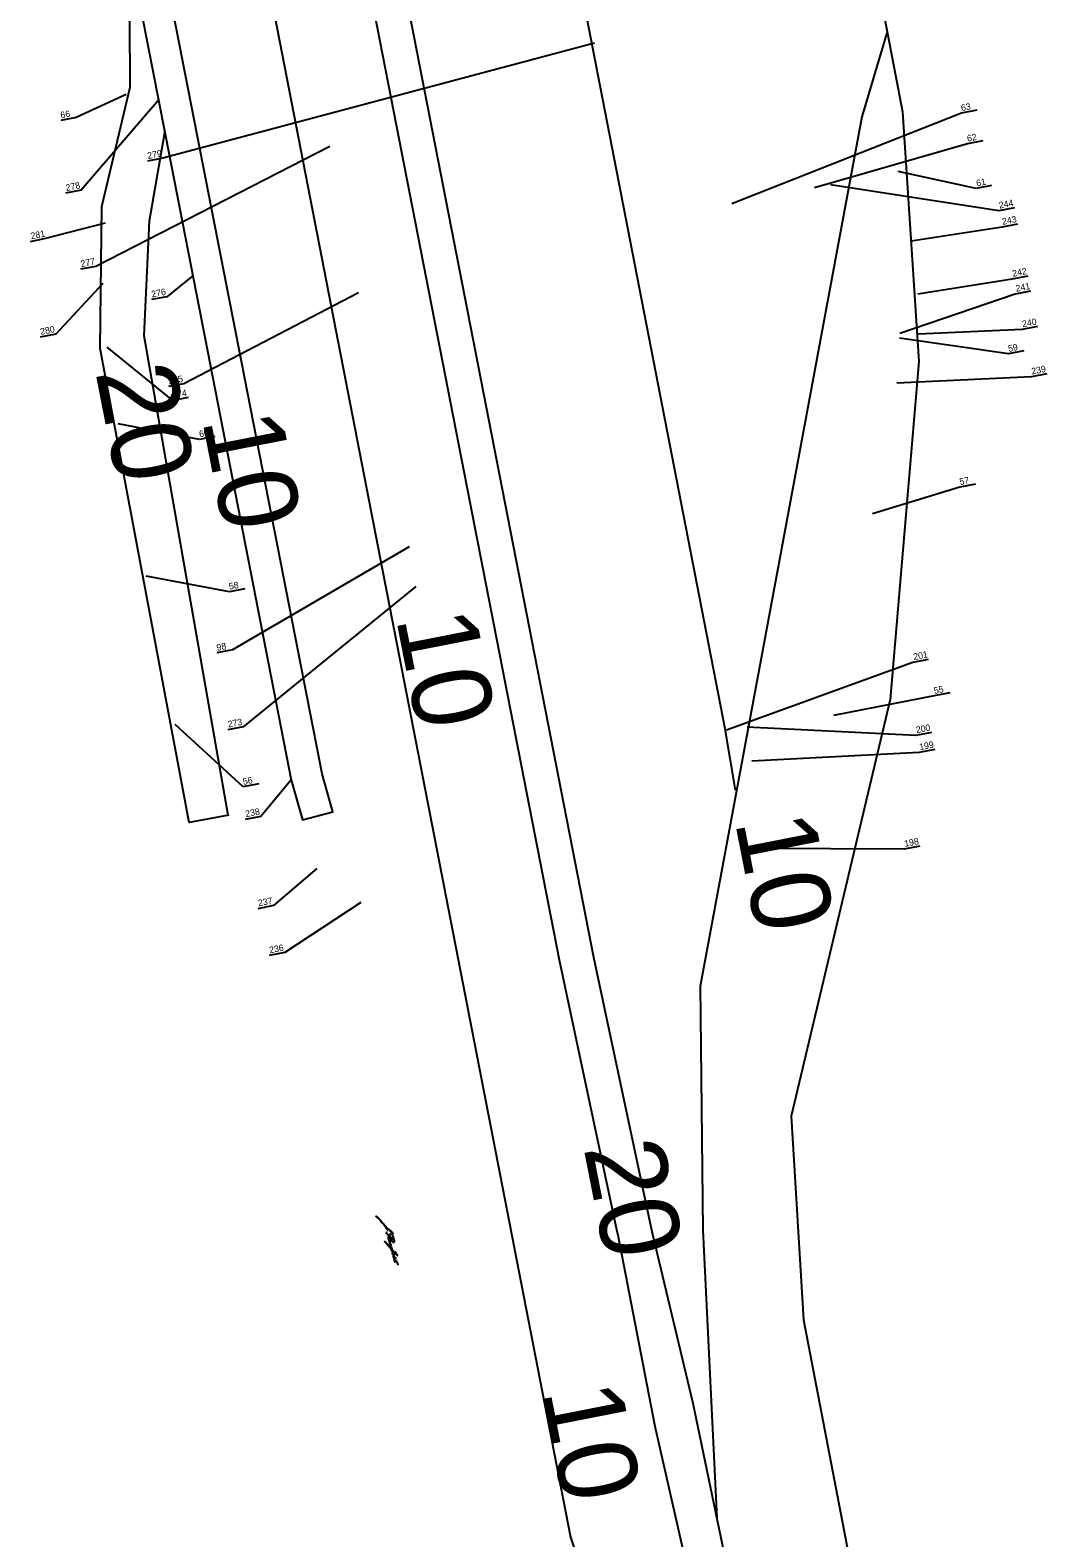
# Model space of a CAD drawing. Extents: x -545967 to -545044, y -1122650 to -1118491.
# Drawn here: x -545644.5 to -545352.2, y -1120534.8 to -1120101.4 of the extents above; entities that cross this region are included whole.
import ezdxf

# ---------------------------------------------------------------- set-up
doc = ezdxf.new("R2010")
doc.units = 0
for name, color, linetype in [('osvětlené plochy-hodnota-obrys', 7, 'Continuous'), ('so180602', 7, 'Continuous'), ('Vrstva 63', 7, 'Continuous')]:
    doc.layers.add(name, color=color, linetype=linetype)

msp = doc.modelspace()

# ---------------------------------------------------------------- linework, layer by layer
at = {"layer": 'osvětlené plochy-hodnota-obrys'}
for points in [[(-545520.97, -1119506.47), (-545505.64, -1119546.72), (-545397.93, -1120102.85)], [(-545441.66, -1120319.91), (-545444.67, -1120302.28), (-545584.85, -1119581.02)], [(-545607.52, -1119727.52), (-545482.54, -1120367.87), (-545465.73, -1120446.74)], [(-545611.11, -1119760.37), (-545492.39, -1120368.61), (-545475.58, -1120447.49)], [(-545605.8, -1119934.36), (-545489.14, -1120534.59)], [(-545587.34, -1120327.06), (-545598.8, -1120329.21), (-545624.38, -1120192.88), (-545623.87, -1120152.06), (-545615.74, -1120117.75), (-545615.95, -1120078.59)], [(-545615.95, -1120078.72), (-545593.53, -1120193.57), (-545569.43, -1120317.04), (-545566.21, -1120328.42), (-545557.45, -1120326.08), (-545560.55, -1120315.17), (-545604.97, -1120087.82)], [(-545398.15, -1120102.16), (-545405.36, -1120126.29), (-545451.85, -1120376.21), (-545451.08, -1120446.35), (-545447.1, -1120529.01)], [(-545397.93, -1120102.85), (-545393.73, -1120124.86), (-545389.03, -1120196.69), (-545397.24, -1120293.85), (-545425.66, -1120413.56)], [(-545587.57, -1120327.02), (-545611.68, -1120189.23), (-545610.12, -1120156.2), (-545605.75, -1120130.8)], [(-545425.66, -1120413.56), (-545422.17, -1120472.14), (-545406.82, -1120552), (-545405.96, -1120682.12)], [(-545413.7, -1120747.46), (-545423.75, -1120695.7), (-545432.65, -1120651.38), (-545447.75, -1120577.89), (-545464.8, -1120502.77), (-545475.48, -1120447.29)], [(-545465.73, -1120446.74), (-545453.92, -1120496.13), (-545438.94, -1120568.39), (-545416.42, -1120682.47), (-545404.15, -1120745.59), (-545418.01, -1120748.3)], [(-545489.14, -1120534.59), (-545478.74, -1120565.98), (-545448.6, -1120720.36), (-545424.84, -1120715.84), (-545418.01, -1120748.3)]]:
    msp.add_lwpolyline(points, dxfattribs=at)
at = {"layer": 'Vrstva 63'}
for p, q in [((-545482.24, -1120105.1), (-545606.32, -1120138.21)), ((-545616.89, -1120119.89), (-545631.2, -1120126.49)), ((-545607.45, -1120121.42), (-545629.82, -1120147.42)), ((-545631.2, -1120126.49), (-545635.64, -1120127.35)), ((-545376.75, -1120125.28), (-545442.71, -1120151.28)), ((-545372.3, -1120124.42), (-545376.75, -1120125.28)), ((-545558.3, -1120134.85), (-545625.54, -1120169.29)), ((-545375.03, -1120134.05), (-545418.99, -1120146.74)), ((-545370.58, -1120133.19), (-545375.03, -1120134.05)), ((-545606.32, -1120138.21), (-545610.77, -1120139.07)), ((-545372.51, -1120146.94), (-545394.9, -1120141.99)), ((-545629.82, -1120147.42), (-545634.26, -1120148.28)), ((-545365.97, -1120153.35), (-545414.36, -1120145.87)), ((-545368.06, -1120146.07), (-545372.51, -1120146.94)), ((-545361.52, -1120152.48), (-545365.97, -1120153.35)), ((-545361.52, -1120152.48), (-545365.97, -1120153.35)), ((-545361.52, -1120152.48), (-545365.97, -1120153.35)), ((-545622.91, -1120156.86), (-545640.02, -1120161.33)), ((-545360.61, -1120157.14), (-545365.06, -1120158)), ((-545360.61, -1120157.14), (-545365.06, -1120158)), ((-545360.61, -1120157.14), (-545365.06, -1120158)), ((-545640.02, -1120161.33), (-545644.47, -1120162.2)), ((-545365.06, -1120158), (-545391.23, -1120162.02)), ((-545625.54, -1120169.29), (-545629.98, -1120170.15)), ((-545623.59, -1120174.2), (-545637.13, -1120188.76)), ((-545597.59, -1120171.95), (-545605.17, -1120178.01)), ((-545362.13, -1120172.95), (-545389.25, -1120177.3)), ((-545357.69, -1120172.08), (-545362.13, -1120172.95)), ((-545357.69, -1120172.08), (-545362.13, -1120172.95)), ((-545357.69, -1120172.08), (-545362.13, -1120172.95)), ((-545605.17, -1120178.01), (-545609.61, -1120178.87)), ((-545550.1, -1120176.89), (-545600.27, -1120203.02)), ((-545361.28, -1120177.28), (-545394.41, -1120188.57)), ((-545356.84, -1120176.41), (-545361.28, -1120177.28)), ((-545356.84, -1120176.41), (-545361.28, -1120177.28)), ((-545356.84, -1120176.41), (-545361.28, -1120177.28)), ((-545359.29, -1120187.46), (-545389.1, -1120188.76)), ((-545354.85, -1120186.59), (-545359.29, -1120187.46)), ((-545354.85, -1120186.59), (-545359.29, -1120187.46)), ((-545354.85, -1120186.59), (-545359.29, -1120187.46)), ((-545637.13, -1120188.76), (-545641.57, -1120189.62)), ((-545363.2, -1120194.47), (-545394.52, -1120189.9)), ((-545603.46, -1120207.9), (-545622.34, -1120192.53)), ((-545358.76, -1120193.61), (-545363.2, -1120194.47)), ((-545356.63, -1120201.04), (-545395.27, -1120202.86)), ((-545352.19, -1120200.18), (-545356.63, -1120201.04)), ((-545352.19, -1120200.18), (-545356.63, -1120201.04)), ((-545352.19, -1120200.18), (-545356.63, -1120201.04)), ((-545600.27, -1120203.02), (-545604.72, -1120203.88)), ((-545599.02, -1120207.04), (-545603.46, -1120207.9)), ((-545595.77, -1120219.04), (-545619.18, -1120214.58)), ((-545591.33, -1120218.18), (-545595.77, -1120219.04)), ((-545377.19, -1120232.74), (-545402.34, -1120240.43)), ((-545372.74, -1120231.87), (-545377.19, -1120232.74)), ((-545535.49, -1120249.95), (-545586.32, -1120279.55)), ((-545587.2, -1120262.84), (-545611.1, -1120258.33)), ((-545533.62, -1120261.28), (-545583.22, -1120301.65)), ((-545582.76, -1120261.98), (-545587.2, -1120262.84)), ((-545586.32, -1120279.55), (-545590.76, -1120280.41)), ((-545390.7, -1120283.15), (-545444.25, -1120302.61)), ((-545386.26, -1120282.29), (-545390.7, -1120283.15)), ((-545386.26, -1120282.29), (-545390.7, -1120283.15)), ((-545380.1, -1120291.94), (-545384.54, -1120292.8)), ((-545384.54, -1120292.8), (-545413.56, -1120298.38)), ((-545583.19, -1120318.95), (-545602.77, -1120301.01)), ((-545583.22, -1120301.65), (-545587.66, -1120302.52)), ((-545389.82, -1120304.15), (-545438.31, -1120301.8)), ((-545385.37, -1120303.28), (-545389.82, -1120304.15)), ((-545385.37, -1120303.28), (-545389.82, -1120304.15)), ((-545388.86, -1120309.03), (-545436.99, -1120311.56)), ((-545384.41, -1120308.17), (-545388.86, -1120309.03)), ((-545384.41, -1120308.17), (-545388.86, -1120309.03)), ((-545578.75, -1120318.08), (-545583.19, -1120318.95)), ((-545569.33, -1120316.8), (-545578.17, -1120327.42)), ((-545578.17, -1120327.42), (-545582.62, -1120328.29)), ((-545393.17, -1120336.82), (-545435.53, -1120336.6)), ((-545388.72, -1120335.96), (-545393.17, -1120336.82)), ((-545388.72, -1120335.96), (-545393.17, -1120336.82)), ((-545562.07, -1120342.36), (-545574.53, -1120353.07)), ((-545549.42, -1120352.2), (-545571.3, -1120366.56)), ((-545574.53, -1120353.07), (-545578.97, -1120353.94)), ((-545571.3, -1120366.56), (-545575.74, -1120367.42))]:
    msp.add_line(p, q, dxfattribs=at)
for points, degree in [([(-545541.08, -1120446.25), (-545540.68, -1120446.69), (-545540.32, -1120447.13), (-545540.19, -1120447.31), (-545540.14, -1120447.37), (-545540.21, -1120447.35), (-545540.38, -1120447.22), (-545540.8, -1120446.81), (-545542.8, -1120444.75), (-545544.12, -1120443.26), (-545544.96, -1120442.38), (-545544.99, -1120442.33), (-545544.93, -1120442.36), (-545544.77, -1120442.5), (-545544.3, -1120442.98), (-545543.81, -1120443.54), (-545542.59, -1120445.06), (-545542.2, -1120445.65), (-545541.86, -1120446.12), (-545541.69, -1120446.28)], 2), ([(-545540.07, -1120448.94), (-545540.34, -1120448.78), (-545540.71, -1120448.51), (-545541.07, -1120448.22), (-545541.62, -1120447.72), (-545542.18, -1120447.14)], 2), ([(-545541.87, -1120446.89), (-545541.88, -1120446.89), (-545541.89, -1120446.88), (-545541.9, -1120446.88)], 2), ([(-545540.86, -1120447.24), (-545540.77, -1120447.23), (-545540.69, -1120447.29), (-545540.6, -1120447.4), (-545540.47, -1120447.58), (-545540.3, -1120447.93), (-545540.14, -1120448.32), (-545540.01, -1120448.71), (-545539.9, -1120449.14), (-545539.85, -1120449.47), (-545539.85, -1120449.7), (-545539.89, -1120449.81), (-545539.95, -1120449.89), (-545540.04, -1120449.91), (-545540.2, -1120449.8), (-545540.45, -1120449.26), (-545540.68, -1120448.72), (-545540.88, -1120448.19), (-545541.11, -1120447.66), (-545541.18, -1120447.43)], 2), ([(-545539.65, -1120452.42), (-545539.61, -1120452.51), (-545539.53, -1120452.64), (-545539.42, -1120452.8), (-545539.25, -1120453.08), (-545539.06, -1120453.37), (-545538.97, -1120453.54), (-545538.91, -1120453.61), (-545538.89, -1120453.67), (-545538.92, -1120453.66), (-545539.02, -1120453.55), (-545539.26, -1120453.28), (-545539.61, -1120452.87), (-545540.41, -1120452.01), (-545540.96, -1120451.43), (-545541.58, -1120450.72), (-545542.23, -1120449.95), (-545542.5, -1120449.65), (-545542.48, -1120449.63), (-545542.43, -1120449.65), (-545542.3, -1120449.79), (-545542.03, -1120450.11), (-545541.6, -1120450.64), (-545540.99, -1120451.45), (-545540.38, -1120452.45), (-545540.03, -1120453.1), (-545539.91, -1120453.29), (-545539.88, -1120453.36), (-545539.92, -1120453.31), (-545540.05, -1120453.13), (-545540.2, -1120453.01), (-545540.35, -1120452.94), (-545540.43, -1120452.92), (-545540.45, -1120452.94), (-545540.43, -1120453.01), (-545540.31, -1120453.24), (-545540.12, -1120453.54), (-545539.96, -1120453.77), (-545539.86, -1120453.89), (-545539.8, -1120453.94), (-545539.74, -1120453.97), (-545539.71, -1120453.98), (-545539.73, -1120454.05), (-545539.72, -1120454.13), (-545539.7, -1120454.2), (-545539.67, -1120454.25), (-545539.73, -1120454.22), (-545539.81, -1120454.16), (-545539.92, -1120454.05), (-545540.01, -1120453.95), (-545540.06, -1120453.91), (-545540.1, -1120453.88), (-545540.13, -1120453.9), (-545540.11, -1120453.98), (-545540.02, -1120454.15), (-545539.93, -1120454.37), (-545539.85, -1120454.52), (-545539.8, -1120454.59), (-545539.77, -1120454.61), (-545539.82, -1120454.63), (-545539.87, -1120454.69), (-545539.87, -1120454.84), (-545539.83, -1120455.02), (-545539.75, -1120455.29), (-545539.66, -1120455.56), (-545539.6, -1120455.68)], 2), ([(-545541, -1120449), (-545540.99, -1120448.92), (-545541.01, -1120448.79), (-545541.11, -1120448.6), (-545541.26, -1120448.39), (-545541.4, -1120448.27), (-545541.46, -1120448.25), (-545541.53, -1120448.28), (-545541.58, -1120448.34), (-545541.58, -1120448.44), (-545541.53, -1120448.54), (-545541.41, -1120448.67), (-545541.3, -1120448.78), (-545541.15, -1120448.93), (-545541.07, -1120449), (-545541, -1120449.03), (-545541.08, -1120449.02), (-545541.25, -1120448.91), (-545541.43, -1120448.86), (-545541.49, -1120448.88), (-545541.52, -1120448.92), (-545541.49, -1120448.99), (-545541.39, -1120449.08), (-545541.28, -1120449.16), (-545541.18, -1120449.23), (-545541.07, -1120449.29), (-545540.95, -1120449.35), (-545540.97, -1120449.36), (-545540.97, -1120449.44), (-545540.96, -1120449.51), (-545540.94, -1120449.58), (-545540.91, -1120449.66), (-545540.95, -1120449.62), (-545541.02, -1120449.54), (-545541.1, -1120449.45), (-545541.19, -1120449.39), (-545541.28, -1120449.39), (-545541.34, -1120449.4), (-545541.37, -1120449.46), (-545541.33, -1120449.53), (-545541.27, -1120449.59), (-545541.19, -1120449.69), (-545541.12, -1120449.77), (-545541.03, -1120449.88), (-545540.92, -1120449.98), (-545540.85, -1120450.05), (-545540.95, -1120449.97), (-545541.05, -1120449.89), (-545541.11, -1120449.87), (-545541.15, -1120449.89), (-545541.17, -1120449.92), (-545541.19, -1120449.99), (-545541.12, -1120450.1), (-545541.06, -1120450.17), (-545540.99, -1120450.25), (-545540.89, -1120450.34), (-545540.81, -1120450.42), (-545540.77, -1120450.46), (-545540.85, -1120450.41), (-545540.96, -1120450.35), (-545541.04, -1120450.33), (-545541.08, -1120450.35), (-545541.07, -1120450.42), (-545541, -1120450.53), (-545540.92, -1120450.62), (-545540.86, -1120450.69), (-545540.79, -1120450.75), (-545540.72, -1120450.79), (-545540.69, -1120450.81), (-545540.77, -1120450.77), (-545540.86, -1120450.74), (-545540.94, -1120450.75), (-545540.98, -1120450.8), (-545540.98, -1120450.86), (-545540.95, -1120450.95), (-545540.9, -1120451.02), (-545540.8, -1120451.11), (-545540.75, -1120451.15), (-545540.69, -1120451.21), (-545540.65, -1120451.3), (-545540.61, -1120451.4), (-545540.57, -1120451.55), (-545540.54, -1120451.64), (-545540.5, -1120451.74), (-545540.5, -1120451.77), (-545540.51, -1120451.72), (-545540.55, -1120451.63), (-545540.59, -1120451.51), (-545540.62, -1120451.45), (-545540.65, -1120451.37), (-545540.69, -1120451.31), (-545540.73, -1120451.26), (-545540.77, -1120451.24), (-545540.83, -1120451.24), (-545540.85, -1120451.28), (-545540.84, -1120451.38), (-545540.82, -1120451.47), (-545540.78, -1120451.56), (-545540.72, -1120451.64), (-545540.69, -1120451.7), (-545540.67, -1120451.72)], 3), ([(-545540.67, -1120451.72), (-545540.65, -1120451.74), (-545540.62, -1120451.76), (-545540.57, -1120451.78), (-545540.5, -1120451.76), (-545540.5, -1120451.78), (-545540.56, -1120451.79), (-545540.64, -1120451.79), (-545540.68, -1120451.79), (-545540.7, -1120451.81), (-545540.73, -1120451.87), (-545540.72, -1120451.95), (-545540.68, -1120452.08), (-545540.64, -1120452.21), (-545540.6, -1120452.32)], 3), ([(-545539.6, -1120453.55), (-545539.62, -1120453.55), (-545539.64, -1120453.54), (-545539.66, -1120453.54)], 2), ([(-545539.42, -1120454.91), (-545539.37, -1120454.96), (-545539.31, -1120455.04), (-545539.29, -1120455.08), (-545539.23, -1120455.2), (-545539.06, -1120455.57), (-545538.93, -1120455.83), (-545538.88, -1120455.93), (-545538.84, -1120456.05), (-545538.8, -1120456.19), (-545538.77, -1120456.28), (-545538.75, -1120456.32)], 2), ([(-545539.3, -1120454.21), (-545539.32, -1120454.23), (-545539.36, -1120454.25), (-545539.37, -1120454.3), (-545539.37, -1120454.36), (-545539.37, -1120454.41), (-545539.35, -1120454.47), (-545539.33, -1120454.54)], 2)]:
    msp.add_open_spline(points, degree=degree, dxfattribs=at)

# ---------------------------------------------------------------- texts
at = {"layer": 'osvětlené plochy-hodnota-obrys'}
for s, p in [('20', (-545625.75, -1120199.6)), ('10', (-545595.05, -1120213.38)), ('10', (-545539.33, -1120270.39)), ('10', (-545441.9, -1120328.83)), ('20', (-545485.39, -1120422.64)), ('10', (-545497.44, -1120492.58))]:
    msp.add_text(s, height=22.781, rotation=281.0956, dxfattribs=at).set_placement(p)
at = {"layer": 'so180602'}
for s, p in [('63', (-545376.68, -1120124.7)), ('66', (-545635.58, -1120126.77)), ('62', (-545374.95, -1120133.47)), ('279', (-545610.58, -1120138.44)), ('61', (-545372.31, -1120146.33)), ('278', (-545634.07, -1120147.65)), ('244', (-545365.78, -1120152.71)), ('243', (-545364.87, -1120157.37)), ('281', (-545644.14, -1120161.53)), ('277', (-545629.78, -1120169.52)), ('242', (-545361.93, -1120172.31)), ('241', (-545360.96, -1120176.61)), ('276', (-545609.42, -1120178.24)), ('280', (-545641.39, -1120188.99)), ('240', (-545359.1, -1120186.82)), ('59', (-545363.14, -1120193.89)), ('275', (-545604.53, -1120203.25)), ('239', (-545356.44, -1120200.41)), ('274', (-545603.39, -1120207.32)), ('60', (-545595.71, -1120218.46)), ('57', (-545377.11, -1120232.15)), ('58', (-545587.14, -1120262.26)), ('98', (-545590.7, -1120279.83)), ('201', (-545390.38, -1120282.49)), ('201', (-545390.38, -1120282.49)), ('55', (-545384.48, -1120292.22)), ('55', (-545384.48, -1120292.22)), ('55', (-545384.48, -1120292.22)), ('55', (-545384.48, -1120292.22)), ('55', (-545384.48, -1120292.22)), ('55', (-545384.48, -1120292.22)), ('55', (-545384.48, -1120292.22)), ('273', (-545587.47, -1120301.88)), ('200', (-545389.63, -1120303.51)), ('200', (-545389.63, -1120303.51)), ('199', (-545388.67, -1120308.4)), ('199', (-545388.67, -1120308.4)), ('56', (-545583.13, -1120318.37)), ('238', (-545582.43, -1120327.65)), ('198', (-545392.98, -1120336.18)), ('198', (-545392.98, -1120336.18)), ('237', (-545578.77, -1120353.3)), ('236', (-545575.55, -1120366.79))]:
    msp.add_text(s, height=1.875, rotation=10.9955, dxfattribs=at).set_placement(p)

doc.saveas('drawing.dxf')
